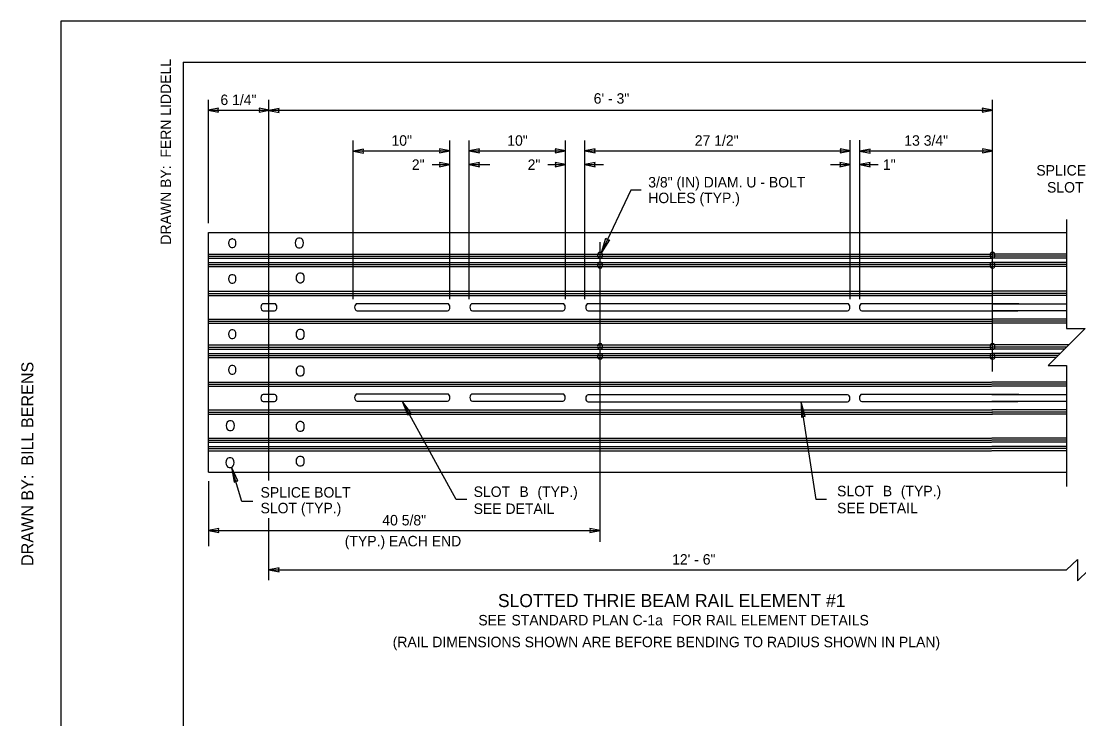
# Model space of a CAD drawing. Extents: x 1312564.2 to 1312581.5, y 1207298.4 to 1207352.6.
# Drawn here: x 1312564.18 to 1312572.27, y 1207347.29 to 1207352.62 of the extents above; entities that cross this region are included whole.
import ezdxf

# ---------------------------------------------------------------- set-up
doc = ezdxf.new("R2010")
doc.units = 0
for name, color, linetype in [('Level 1', 7, 'Continuous'), ('Level 14', 7, 'Continuous'), ('Level 15', 7, 'Continuous'), ('Level 2', 7, 'Continuous'), ('Level 20', 7, 'Continuous'), ('Level 6', 7, 'Continuous'), ('Level 62', 7, 'Continuous'), ('Level 8', 7, 'Continuous')]:
    doc.layers.add(name, color=color, linetype=linetype)

msp = doc.modelspace()

# ---------------------------------------------------------------- linework, layer by layer
at = {"layer": 'Level 1'}
for q in [(1312565.4155, 1207341.9333), (1312581.1655, 1207352.3083)]:
    msp.add_line((1312565.4155, 1207352.3083), q, dxfattribs=at)
at = {"layer": 'Level 14'}
for points in [[(1312567.5847, 1207348.9636), (1312567.5047, 1207348.9636), (1312567.0914, 1207349.7159)], [(1312570.3376, 1207348.9636), (1312570.2577, 1207348.9636), (1312570.1427, 1207349.709)]]:
    msp.add_lwpolyline(points, dxfattribs=at)
for points in [[(1312567.0914, 1207349.7159), (1312567.1332, 1207349.6087), (1312567.1437, 1207349.6205), (1312567.1593, 1207349.6231)], [(1312570.1427, 1207349.709), (1312570.1444, 1207349.5939), (1312570.1584, 1207349.6013), (1312570.1739, 1207349.5982)], [(1312565.7857, 1207349.2101), (1312565.8049, 1207349.0967), (1312565.8176, 1207349.1061), (1312565.8334, 1207349.1055)]]:
    msp.add_lwpolyline(points, close=True, dxfattribs=at)
at = {"layer": 'Level 15'}
for p, q in [((1312565.609, 1207351.0762), (1312565.609, 1207352.0196)), ((1312566.0709, 1207349.1092), (1312566.0709, 1207352.0196)), ((1312571.6068, 1207349.9426), (1312571.6068, 1207352.0196)), ((1312565.6102, 1207351.9396), (1312566.0706, 1207351.9396)), ((1312566.0706, 1207351.9396), (1312571.6068, 1207351.9396)), ((1312566.7163, 1207350.4968), (1312566.7163, 1207351.7085)), ((1312567.4545, 1207350.4968), (1312567.4545, 1207351.7085)), ((1312567.6022, 1207350.4968), (1312567.6022, 1207351.7085)), ((1312568.3404, 1207350.4968), (1312568.3404, 1207351.7085)), ((1312568.488, 1207350.4968), (1312568.488, 1207351.7085)), ((1312570.5918, 1207350.4968), (1312570.5918, 1207351.7102)), ((1312568.488, 1207351.6285), (1312570.5112, 1207351.6285)), ((1312570.518, 1207350.4968), (1312570.518, 1207351.5179)), ((1312568.6043, 1207348.6399), (1312568.6043, 1207350.9301)), ((1312572.0324, 1207349.9888), (1312572.173, 1207349.9888)), ((1312572.173, 1207349.9888), (1312572.173, 1207349.0631)), ((1312565.609, 1207349.1052), (1312565.609, 1207348.6072)), ((1312566.0709, 1207348.5853), (1312566.0709, 1207348.8224)), ((1312565.609, 1207348.726), (1312568.6043, 1207348.726)), ((1312566.0709, 1207348.3466), (1312566.0709, 1207348.6823)), ((1312566.0709, 1207348.4261), (1312572.1726, 1207348.4261)), ((1312571.7575, 1207348.4261), (1312572.1738, 1207348.4261))]:
    msp.add_line(p, q, dxfattribs=at)
for points in [[(1312568.9187, 1207351.3296), (1312568.8387, 1207351.3296), (1312568.6139, 1207350.8508)], [(1312572.1734, 1207351.1055), (1312572.1734, 1207350.2708), (1312572.3144, 1207350.2708), (1312572.0324, 1207349.9888)], [(1312565.9476, 1207348.9494), (1312565.8637, 1207348.9494), (1312565.7857, 1207349.2101)], [(1312572.1726, 1207348.4261), (1312572.2571, 1207348.5042), (1312572.2571, 1207348.3428), (1312572.34, 1207348.4249)]]:
    msp.add_lwpolyline(points, dxfattribs=at)
for points in [[(1312568.6141, 1207350.8512), (1312568.6487, 1207350.9609), (1312568.66, 1207350.9498), (1312568.6758, 1207350.9483)], [(1312565.609, 1207348.726), (1312565.6876, 1207348.7105), (1312565.684, 1207348.726), (1312565.6876, 1207348.7414)], [(1312568.6043, 1207348.726), (1312568.5257, 1207348.7414), (1312568.5294, 1207348.726), (1312568.5257, 1207348.7105)], [(1312566.0702, 1207348.4265), (1312566.1488, 1207348.4111), (1312566.1452, 1207348.4265), (1312566.1488, 1207348.442)]]:
    msp.add_lwpolyline(points, close=True, dxfattribs=at)
at = {"layer": 'Level 2'}
msp.add_lwpolyline([(1312564.478, 1207341.6208), (1312581.478, 1207341.6208), (1312581.478, 1207352.6208), (1312564.478, 1207352.6208)], close=True, dxfattribs=at)
at = {"layer": 'Level 6'}
for p, q in [((1312570.518, 1207351.5179), (1312570.518, 1207351.7102)), ((1312566.7167, 1207351.6285), (1312567.4545, 1207351.6285)), ((1312567.6022, 1207351.6285), (1312568.3404, 1207351.6285)), ((1312570.5981, 1207351.6285), (1312571.6068, 1207351.6285)), ((1312567.3199, 1207351.5239), (1312567.4563, 1207351.5239)), ((1312567.6022, 1207351.5239), (1312567.7621, 1207351.5239)), ((1312568.2039, 1207351.5239), (1312568.3404, 1207351.5239)), ((1312568.488, 1207351.5239), (1312568.6312, 1207351.5239)), ((1312570.3677, 1207351.5239), (1312570.518, 1207351.5239)), ((1312570.5918, 1207351.5239), (1312570.7332, 1207351.5239)), ((1312565.796, 1207350.9556), (1312565.7847, 1207350.9556)), ((1312566.3093, 1207350.9615), (1312566.2967, 1207350.9615)), ((1312565.7847, 1207350.8903), (1312565.796, 1207350.8903)), ((1312566.2967, 1207350.889), (1312566.3093, 1207350.889)), ((1312568.6082, 1207350.853), (1312568.6007, 1207350.853)), ((1312571.6104, 1207350.853), (1312571.6028, 1207350.853)), ((1312565.609, 1207350.8397), (1312571.5997, 1207350.8397)), ((1312565.609, 1207350.824), (1312571.5997, 1207350.824)), ((1312565.609, 1207350.8082), (1312571.5997, 1207350.8082)), ((1312565.609, 1207350.7756), (1312571.6068, 1207350.7756)), ((1312568.6007, 1207350.8094), (1312568.6082, 1207350.8094)), ((1312568.6082, 1207350.7773), (1312568.6007, 1207350.7773)), ((1312571.8072, 1207350.8397), (1312571.6022, 1207350.8397)), ((1312571.8072, 1207350.824), (1312571.6022, 1207350.824)), ((1312571.8072, 1207350.8082), (1312571.6022, 1207350.8082)), ((1312571.8072, 1207350.7756), (1312571.6022, 1207350.7756)), ((1312571.6028, 1207350.8094), (1312571.6104, 1207350.8094)), ((1312571.6104, 1207350.7773), (1312571.6028, 1207350.7773)), ((1312572.1734, 1207350.8397), (1312571.8072, 1207350.8397)), ((1312572.1734, 1207350.824), (1312571.8072, 1207350.824)), ((1312572.1734, 1207350.8082), (1312571.8072, 1207350.8082)), ((1312572.1734, 1207350.7756), (1312571.8072, 1207350.7756)), ((1312565.609, 1207350.7598), (1312571.6068, 1207350.7598)), ((1312565.609, 1207350.7441), (1312571.6068, 1207350.7441)), ((1312565.796, 1207350.6826), (1312565.7847, 1207350.6826)), ((1312566.3163, 1207350.6938), (1312566.3037, 1207350.6938)), ((1312568.6007, 1207350.7338), (1312568.6082, 1207350.7338)), ((1312571.8072, 1207350.7598), (1312571.6022, 1207350.7598)), ((1312571.8072, 1207350.7441), (1312571.6022, 1207350.7441)), ((1312571.6028, 1207350.7338), (1312571.6104, 1207350.7338)), ((1312572.1734, 1207350.7598), (1312571.8072, 1207350.7598)), ((1312572.1734, 1207350.7441), (1312571.8072, 1207350.7441)), ((1312565.7847, 1207350.6173), (1312565.796, 1207350.6173)), ((1312566.3037, 1207350.6213), (1312566.3163, 1207350.6213)), ((1312565.609, 1207350.5559), (1312571.5997, 1207350.5559)), ((1312565.609, 1207350.5401), (1312571.5997, 1207350.5401)), ((1312565.609, 1207350.5243), (1312571.5997, 1207350.5243)), ((1312571.8072, 1207350.5559), (1312571.6022, 1207350.5559)), ((1312571.8072, 1207350.5401), (1312571.6022, 1207350.5401)), ((1312571.8072, 1207350.5243), (1312571.6022, 1207350.5243)), ((1312572.1734, 1207350.5559), (1312571.8072, 1207350.5559)), ((1312572.1734, 1207350.5401), (1312571.8072, 1207350.5401)), ((1312572.1734, 1207350.5243), (1312571.8072, 1207350.5243)), ((1312566.1132, 1207350.4607), (1312566.0282, 1207350.4607)), ((1312567.4373, 1207350.4607), (1312566.7455, 1207350.4607)), ((1312568.3192, 1207350.4607), (1312567.6274, 1207350.4607)), ((1312570.4969, 1207350.4607), (1312568.5136, 1207350.4607)), ((1312570.6075, 1207350.4607), (1312570.6074, 1207350.4608)), ((1312571.8072, 1207350.4607), (1312570.6075, 1207350.4607)), ((1312571.6022, 1207350.4607), (1312572.1734, 1207350.4607)), ((1312566.0282, 1207350.4063), (1312566.1132, 1207350.4063)), ((1312566.7455, 1207350.4063), (1312567.4373, 1207350.4063)), ((1312567.6274, 1207350.4063), (1312568.3192, 1207350.4063)), ((1312568.5136, 1207350.4063), (1312570.4969, 1207350.4063)), ((1312570.6074, 1207350.4065), (1312570.6075, 1207350.4063)), ((1312570.6075, 1207350.4063), (1312571.8006, 1207350.4063)), ((1312572.1734, 1207350.4063), (1312571.6023, 1207350.4063)), ((1312565.609, 1207350.3427), (1312571.5997, 1207350.3427)), ((1312565.609, 1207350.3269), (1312571.5997, 1207350.3269)), ((1312565.609, 1207350.3112), (1312571.5997, 1207350.3112)), ((1312571.8072, 1207350.3427), (1312571.6022, 1207350.3427)), ((1312571.8072, 1207350.3269), (1312571.6022, 1207350.3269)), ((1312571.8072, 1207350.3112), (1312571.6022, 1207350.3112)), ((1312572.1734, 1207350.3427), (1312571.8072, 1207350.3427)), ((1312572.1734, 1207350.3269), (1312571.8072, 1207350.3269)), ((1312572.1734, 1207350.3112), (1312571.8072, 1207350.3112)), ((1312565.796, 1207350.2606), (1312565.7847, 1207350.2606)), ((1312566.3163, 1207350.2629), (1312566.3037, 1207350.2629)), ((1312565.609, 1207350.1453), (1312571.6068, 1207350.1453)), ((1312565.609, 1207350.1296), (1312571.6068, 1207350.1296)), ((1312565.7847, 1207350.1954), (1312565.796, 1207350.1954)), ((1312566.3037, 1207350.1904), (1312566.3163, 1207350.1904)), ((1312568.6082, 1207350.1557), (1312568.6007, 1207350.1557)), ((1312571.6104, 1207350.1557), (1312571.6028, 1207350.1557)), ((1312571.8072, 1207350.1453), (1312571.6068, 1207350.1453)), ((1312571.8072, 1207350.1296), (1312571.6068, 1207350.1296)), ((1312572.1889, 1207350.1453), (1312571.8072, 1207350.1453)), ((1312572.1731, 1207350.1296), (1312571.8072, 1207350.1296)), ((1312565.609, 1207350.1143), (1312571.6068, 1207350.1143)), ((1312565.609, 1207350.0806), (1312570.3883, 1207350.0806)), ((1312565.609, 1207350.0648), (1312571.6068, 1207350.0648)), ((1312565.609, 1207350.0491), (1312571.6068, 1207350.0491)), ((1312568.6007, 1207350.1122), (1312568.6082, 1207350.1122)), ((1312568.6082, 1207350.0801), (1312568.6007, 1207350.0801)), ((1312568.6007, 1207350.0365), (1312568.6082, 1207350.0365)), ((1312570.3883, 1207350.0806), (1312571.5997, 1207350.0806)), ((1312571.8072, 1207350.0806), (1312571.6022, 1207350.0806)), ((1312571.6028, 1207350.1122), (1312571.6104, 1207350.1122)), ((1312571.6104, 1207350.0801), (1312571.6028, 1207350.0801)), ((1312571.6028, 1207350.0365), (1312571.6104, 1207350.0365)), ((1312571.8072, 1207350.1143), (1312571.6068, 1207350.1143)), ((1312571.8072, 1207350.0648), (1312571.6068, 1207350.0648)), ((1312571.8072, 1207350.0491), (1312571.6068, 1207350.0491)), ((1312572.1579, 1207350.1143), (1312571.8072, 1207350.1143)), ((1312572.1242, 1207350.0806), (1312571.8072, 1207350.0806)), ((1312572.1084, 1207350.0648), (1312571.8072, 1207350.0648)), ((1312572.0926, 1207350.0491), (1312571.8072, 1207350.0491)), ((1312565.796, 1207349.9876), (1312565.7847, 1207349.9876)), ((1312566.3163, 1207349.9825), (1312566.3037, 1207349.9825)), ((1312565.7847, 1207349.9224), (1312565.796, 1207349.9224)), ((1312566.3037, 1207349.91), (1312566.3163, 1207349.91)), ((1312565.609, 1207349.8615), (1312571.5997, 1207349.8615)), ((1312565.609, 1207349.8457), (1312571.5997, 1207349.8457)), ((1312565.609, 1207349.8305), (1312571.5997, 1207349.8305)), ((1312571.8072, 1207349.8615), (1312571.6022, 1207349.8615)), ((1312571.8072, 1207349.8457), (1312571.6022, 1207349.8457)), ((1312571.8072, 1207349.8305), (1312571.6022, 1207349.8305)), ((1312572.173, 1207349.8615), (1312571.8072, 1207349.8615)), ((1312572.173, 1207349.8457), (1312571.8072, 1207349.8457)), ((1312572.173, 1207349.8305), (1312571.8072, 1207349.8305)), ((1312566.1132, 1207349.7668), (1312566.0282, 1207349.7668)), ((1312566.0282, 1207349.7124), (1312566.1132, 1207349.7124)), ((1312567.4373, 1207349.7703), (1312566.7455, 1207349.7703)), ((1312566.7455, 1207349.7159), (1312567.4373, 1207349.7159)), ((1312568.3192, 1207349.7703), (1312567.6274, 1207349.7703)), ((1312567.6274, 1207349.7159), (1312568.3192, 1207349.7159)), ((1312570.4969, 1207349.7643), (1312568.5136, 1207349.7643)), ((1312570.6075, 1207349.7675), (1312570.6074, 1207349.7676)), ((1312570.6074, 1207349.7132), (1312570.6075, 1207349.7131)), ((1312571.8072, 1207349.7675), (1312570.6075, 1207349.7675)), ((1312570.6075, 1207349.7131), (1312571.8006, 1207349.7131)), ((1312571.6022, 1207349.7675), (1312572.173, 1207349.7675)), ((1312572.173, 1207349.7131), (1312571.6023, 1207349.7131)), ((1312565.609, 1207349.6488), (1312571.6068, 1207349.6488)), ((1312565.609, 1207349.6325), (1312571.6068, 1207349.6325)), ((1312568.5136, 1207349.7099), (1312570.4969, 1207349.7099)), ((1312571.8072, 1207349.6488), (1312571.6022, 1207349.6488)), ((1312571.8072, 1207349.6325), (1312571.6022, 1207349.6325)), ((1312572.173, 1207349.6488), (1312571.8072, 1207349.6488)), ((1312572.173, 1207349.6325), (1312571.8072, 1207349.6325)), ((1312565.609, 1207349.6168), (1312571.6068, 1207349.6168)), ((1312565.7827, 1207349.5646), (1312565.7702, 1207349.5646)), ((1312566.3163, 1207349.5591), (1312566.3037, 1207349.5591)), ((1312571.8072, 1207349.6168), (1312571.6022, 1207349.6168)), ((1312572.173, 1207349.6168), (1312571.8072, 1207349.6168)), ((1312565.7702, 1207349.4921), (1312565.7827, 1207349.4921)), ((1312566.3037, 1207349.4866), (1312566.3163, 1207349.4866)), ((1312565.609, 1207349.4335), (1312571.5997, 1207349.4335)), ((1312565.609, 1207349.4177), (1312571.5997, 1207349.4177)), ((1312565.609, 1207349.402), (1312571.5997, 1207349.402)), ((1312571.8072, 1207349.4335), (1312571.6022, 1207349.4335)), ((1312571.8072, 1207349.4177), (1312571.6022, 1207349.4177)), ((1312571.8072, 1207349.402), (1312571.6022, 1207349.402)), ((1312572.173, 1207349.4335), (1312571.8072, 1207349.4335)), ((1312572.173, 1207349.4177), (1312571.8072, 1207349.4177)), ((1312572.173, 1207349.402), (1312571.8072, 1207349.402)), ((1312565.609, 1207349.3687), (1312571.5997, 1207349.3687)), ((1312565.609, 1207349.353), (1312571.5997, 1207349.353)), ((1312565.609, 1207349.3372), (1312571.5997, 1207349.3372)), ((1312571.8072, 1207349.3687), (1312571.6022, 1207349.3687)), ((1312571.8072, 1207349.353), (1312571.6022, 1207349.353)), ((1312571.8072, 1207349.3372), (1312571.6022, 1207349.3372)), ((1312572.173, 1207349.3687), (1312571.8072, 1207349.3687)), ((1312572.173, 1207349.353), (1312571.8072, 1207349.353)), ((1312572.173, 1207349.3372), (1312571.8072, 1207349.3372)), ((1312565.7797, 1207349.2818), (1312565.7671, 1207349.2818)), ((1312566.3163, 1207349.2931), (1312566.3037, 1207349.2931)), ((1312565.7671, 1207349.2093), (1312565.7797, 1207349.2093)), ((1312566.3037, 1207349.2206), (1312566.3163, 1207349.2206))]:
    msp.add_line(p, q, dxfattribs=at)
for points in [[(1312565.606, 1207351.9407), (1312565.6846, 1207351.9253), (1312565.6809, 1207351.9407), (1312565.6846, 1207351.9562)], [(1312566.0741, 1207351.9393), (1312565.9955, 1207351.9547), (1312565.9991, 1207351.9393), (1312565.9955, 1207351.9239)], [(1312566.0697, 1207351.9388), (1312566.1483, 1207351.9234), (1312566.1446, 1207351.9388), (1312566.1483, 1207351.9542)], [(1312571.6068, 1207351.9396), (1312571.5282, 1207351.9551), (1312571.5318, 1207351.9396), (1312571.5282, 1207351.9242)], [(1312566.7171, 1207351.6276), (1312566.7956, 1207351.6122), (1312566.792, 1207351.6276), (1312566.7956, 1207351.6431)], [(1312567.4545, 1207351.6285), (1312567.3759, 1207351.6439), (1312567.3796, 1207351.6285), (1312567.3759, 1207351.6131)], [(1312567.6022, 1207351.6285), (1312567.6807, 1207351.6131), (1312567.6771, 1207351.6285), (1312567.6807, 1207351.6439)], [(1312568.3403, 1207351.6285), (1312568.2618, 1207351.6439), (1312568.2654, 1207351.6285), (1312568.2618, 1207351.6131)], [(1312568.488, 1207351.6285), (1312568.5666, 1207351.6131), (1312568.5629, 1207351.6285), (1312568.5666, 1207351.6439)], [(1312570.5203, 1207351.6303), (1312570.4417, 1207351.6457), (1312570.4453, 1207351.6303), (1312570.4417, 1207351.6149)], [(1312570.5924, 1207351.6274), (1312570.671, 1207351.612), (1312570.6673, 1207351.6274), (1312570.671, 1207351.6428)], [(1312571.608, 1207351.6302), (1312571.5295, 1207351.6456), (1312571.5331, 1207351.6302), (1312571.5295, 1207351.6148)], [(1312567.4545, 1207351.5239), (1312567.3759, 1207351.5393), (1312567.3796, 1207351.5239), (1312567.3759, 1207351.5085)], [(1312567.6022, 1207351.5239), (1312567.6807, 1207351.5085), (1312567.6771, 1207351.5239), (1312567.6807, 1207351.5393)], [(1312568.3403, 1207351.5239), (1312568.2618, 1207351.5393), (1312568.2654, 1207351.5239), (1312568.2618, 1207351.5085)], [(1312568.488, 1207351.5239), (1312568.5666, 1207351.5085), (1312568.5629, 1207351.5239), (1312568.5666, 1207351.5393)], [(1312570.518, 1207351.5239), (1312570.4394, 1207351.5393), (1312570.443, 1207351.5239), (1312570.4394, 1207351.5085)], [(1312570.5918, 1207351.5239), (1312570.6704, 1207351.5085), (1312570.6667, 1207351.5239), (1312570.6704, 1207351.5393)]]:
    msp.add_lwpolyline(points, close=True, dxfattribs=at)
for centre, major_axis in [((1312565.7848, 1207350.9228), (0, -0.0326)), ((1312565.7961, 1207350.9228), (0, 0.0326)), ((1312566.2968, 1207350.9251), (0, -0.0363)), ((1312566.3094, 1207350.9251), (0, 0.0363)), ((1312568.6007, 1207350.8311), (0, -0.0218)), ((1312568.6083, 1207350.8311), (0, 0.0218)), ((1312571.6029, 1207350.8311), (0, -0.0218)), ((1312571.6104, 1207350.8311), (0, 0.0218)), ((1312568.6007, 1207350.7555), (0, -0.0218)), ((1312568.6083, 1207350.7555), (0, 0.0218)), ((1312571.6029, 1207350.7555), (0, -0.0218)), ((1312571.6104, 1207350.7555), (0, 0.0218)), ((1312565.7848, 1207350.6501), (0, -0.0326)), ((1312565.7961, 1207350.6501), (0, 0.0326)), ((1312566.3038, 1207350.6578), (0, -0.0363)), ((1312566.3164, 1207350.6578), (0, 0.0363)), ((1312566.0281, 1207350.4337), (0, -0.0272)), ((1312566.1131, 1207350.4337), (0, 0.0272)), ((1312566.7454, 1207350.4337), (0, -0.0272)), ((1312567.4372, 1207350.4337), (0, 0.0272)), ((1312567.6273, 1207350.4337), (0, -0.0272)), ((1312568.3191, 1207350.4337), (0, 0.0272)), ((1312568.5135, 1207350.4337), (0, -0.0272)), ((1312570.4969, 1207350.4337), (0, 0.0272)), ((1312570.6074, 1207350.4337), (0, -0.0272)), ((1312565.7848, 1207350.2281), (0, -0.0326)), ((1312565.7961, 1207350.2281), (0, 0.0326)), ((1312566.3038, 1207350.2267), (0, -0.0363)), ((1312566.3164, 1207350.2267), (0, 0.0363)), ((1312568.6007, 1207350.1339), (0, -0.0218)), ((1312568.6083, 1207350.1339), (0, 0.0218)), ((1312571.6029, 1207350.1339), (0, -0.0218)), ((1312571.6104, 1207350.1339), (0, 0.0218)), ((1312568.6007, 1207350.0582), (0, -0.0218)), ((1312568.6083, 1207350.0582), (0, 0.0218)), ((1312571.6029, 1207350.0582), (0, -0.0218)), ((1312571.6104, 1207350.0582), (0, 0.0218)), ((1312565.7848, 1207349.9551), (0, -0.0326)), ((1312565.7961, 1207349.9551), (0, 0.0326)), ((1312566.3038, 1207349.9463), (0, -0.0363)), ((1312566.3164, 1207349.9463), (0, 0.0363)), ((1312566.0281, 1207349.7398), (0, -0.0272)), ((1312566.1131, 1207349.7398), (0, 0.0272)), ((1312566.7454, 1207349.7432), (0, -0.0272)), ((1312567.4372, 1207349.7432), (0, 0.0272)), ((1312567.6273, 1207349.7432), (0, -0.0272)), ((1312568.3191, 1207349.7432), (0, 0.0272)), ((1312568.5135, 1207349.7372), (0, -0.0272)), ((1312570.4969, 1207349.7372), (0, 0.0272)), ((1312570.6074, 1207349.7404), (0, -0.0272)), ((1312565.7703, 1207349.5285), (0, -0.0363)), ((1312565.7828, 1207349.5285), (0, 0.0363)), ((1312566.3038, 1207349.5229), (0, -0.0363)), ((1312566.3164, 1207349.5229), (0, 0.0363)), ((1312565.7672, 1207349.2458), (0, -0.0363)), ((1312565.7798, 1207349.2458), (0, 0.0363)), ((1312566.3038, 1207349.257), (0, -0.0363)), ((1312566.3164, 1207349.257), (0, 0.0363))]:
    msp.add_ellipse(centre, major_axis=major_axis, ratio=0.694444, start_param=3.141593, end_param=6.283185, dxfattribs=at)
at = {"layer": 'Level 8'}
for p, q in [((1312565.609, 1207349.172), (1312565.609, 1207351.0056)), ((1312565.609, 1207351.0056), (1312572.1734, 1207351.0056)), ((1312565.609, 1207349.172), (1312572.173, 1207349.172))]:
    msp.add_line(p, q, dxfattribs=at)

# ---------------------------------------------------------------- texts
at = {"layer": 'Level 20'}
for s, height, p in [('6 1/4"', 0.07995, (1312565.7, 1207351.9796)), ('6\' - 3"', 0.07995, (1312568.5555, 1207351.9901)), ('10"', 0.07995, (1312567.0086, 1207351.6685)), ('10"', 0.07995, (1312567.8943, 1207351.6685)), ('27 1/2"', 0.07995, (1312569.329, 1207351.6685)), ('13 3/4"', 0.07995, (1312570.9319, 1207351.6685)), ('2"', 0.07995, (1312567.1641, 1207351.4839)), ('2"', 0.07995, (1312568.0504, 1207351.4839)), ('1"', 0.07995, (1312570.7684, 1207351.4839)), ('SPLICE BOLT ', 0.079953, (1312571.9422, 1207351.4407)), ('3/8" (IN) DIAM. U - BOLT', 0.079953, (1312568.973, 1207351.3496)), ('SLOT (TYP.)', 0.079953, (1312572.0238, 1207351.3108)), ('HOLES (TYP.)', 0.079953, (1312568.973, 1207351.2297)), ('SLOT ', 0.07995, (1312567.6371, 1207348.9836)), ('B', 0.08, (1312567.9871, 1207348.9836)), ('  (TYP.)', 0.07995, (1312568.0655, 1207348.9836)), ('SLOT ', 0.07995, (1312570.4176, 1207348.9886)), ('B', 0.08, (1312570.7676, 1207348.9886)), ('  (TYP.) ', 0.07995, (1312570.846, 1207348.9886)), ('SPLICE BOLT ', 0.079953, (1312566.0069, 1207348.9785)), ('SLOT (TYP.)', 0.079953, (1312566.0069, 1207348.8586)), ('SEE DETAIL', 0.07995, (1312567.6371, 1207348.8536)), ('SEE DETAIL', 0.07995, (1312570.4176, 1207348.8586)), ('40 5/8"', 0.07995, (1312566.9384, 1207348.7658)), ('(TYP.) EACH END', 0.079953, (1312566.6512, 1207348.6059)), ('12\' - 6"', 0.07995, (1312569.1555, 1207348.4661)), ('SLOTTED THRIE BEAM RAIL ELEMENT #1', 0.099942, (1312567.8232, 1207348.1415)), ('SEE ', 0.07995, (1312567.6731, 1207348.0015)), ('STANDARD PLAN C-1a ', 0.079953, (1312567.9265, 1207348.0015)), ('FOR RAIL ELEMENT DETAILS', 0.079953, (1312569.1574, 1207348.0015)), ('(RAIL DIMENSIONS SHOWN ARE BEFORE BENDING TO RADIUS SHOWN IN PLAN)', 0.079953, (1312567.0178, 1207347.8347))]:
    msp.add_text(s, height=height, dxfattribs=at).set_placement(p)
at = {"layer": 'Level 62'}
for s, height, p in [('DRAWN BY:  FERN LIDDELL', 0.079953, (1312565.3216, 1207350.9123)), ('DRAWN BY:  BILL BERENS', 0.09216, (1312564.2689, 1207348.4556))]:
    msp.add_text(s, height=height, rotation=90, dxfattribs=at).set_placement(p)

doc.saveas('drawing.dxf')
